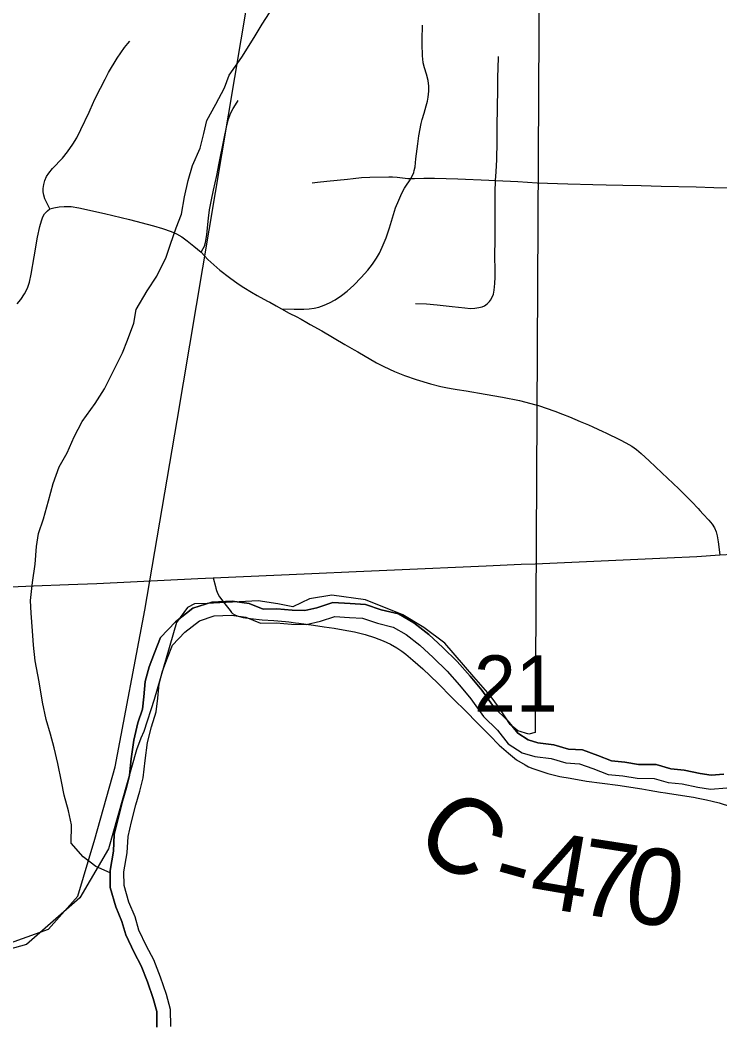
# Model space of a CAD drawing. Extents: x 0 to 191, y 0 to 55.
# Drawn here: x 143.5787 to 143.8392, y 23.9869 to 24.3604 of the extents above; entities that cross this region are included whole.
import ezdxf

# ---------------------------------------------------------------- set-up
doc = ezdxf.new("R2010")
doc.units = 0
for name, color, linetype in [('GM_X_City_Street', 7, 'Continuous'), ('GM_X_Corporation', 7, 'Continuous'), ('GM_X_County_Road', 7, 'Continuous'), ('GM_X_County_Road_Text', 7, 'Continuous'), ('GM_X_Major_River', 7, 'Continuous'), ('GM_X_Minor_River', 7, 'Continuous'), ('GM_X_Rail_Line', 7, 'Continuous'), ('GM_X_Section_Text', 7, 'Continuous'), ('GM_X_State_Route', 7, 'Continuous'), ('GM_X_Township_Road', 7, 'Continuous')]:
    doc.layers.add(name, color=color, linetype=linetype)

msp = doc.modelspace()

# ---------------------------------------------------------------- linework, layer by layer
at = {"layer": 'GM_X_City_Street'}
for points in [[(143.72412, 24.30142), (143.72486, 24.3027), (143.72525, 24.30362), (143.72539, 24.30431), (143.72567, 24.30567), (143.72603, 24.30874), (143.72668, 24.31426), (143.72711, 24.31732), (143.72792, 24.32189), (143.7283, 24.32339), (143.72903, 24.32575), (143.72981, 24.32842), (143.73027, 24.33022), (143.73059, 24.33173), (143.73085, 24.33388), (143.73085, 24.33573), (143.73055, 24.33787), (143.72996, 24.34028), (143.72923, 24.34265), (143.72874, 24.34444), (143.72852, 24.34597), (143.72843, 24.34689), (143.7284, 24.34812), (143.72831, 24.3506), (143.72835, 24.35495), (143.7284, 24.35646), (143.72847, 24.35731), (143.72845, 24.35801), (143.72847, 24.35853)], [(143.58969, 24.29003), (143.58838, 24.2928), (143.58793, 24.29375), (143.58747, 24.29516), (143.58728, 24.29639), (143.58726, 24.29763), (143.58747, 24.29917), (143.58789, 24.30066), (143.58854, 24.30208), (143.58938, 24.30338), (143.59077, 24.30505), (143.59439, 24.30892), (143.59636, 24.31133), (143.59831, 24.31414), (143.59974, 24.31654), (143.60131, 24.31959), (143.60435, 24.32607), (143.60472, 24.32692), (143.6056, 24.3289), (143.60651, 24.33088), (143.60855, 24.33507), (143.61028, 24.33836), (143.61163, 24.34081), (143.61483, 24.34623), (143.61756, 24.35011), (143.61882, 24.35163), (143.61952, 24.35252)], [(143.7515, 24.25398), (143.75259, 24.25473), (143.75345, 24.25559), (143.75381, 24.25608), (143.75441, 24.25713), (143.75485, 24.25827), (143.75516, 24.25976), (143.75535, 24.26224), (143.75545, 24.26464), (143.75549, 24.26632), (143.75549, 24.26738), (143.75548, 24.2682), (143.7554, 24.27149), (143.75542, 24.27487), (143.75545, 24.2764), (143.75549, 24.27824), (143.75551, 24.28099), (143.75556, 24.28407), (143.75553, 24.28686), (143.75554, 24.29736), (143.7556, 24.29952), (143.75566, 24.30064), (143.75583, 24.30384), (143.75611, 24.30848), (143.75625, 24.31498), (143.75628, 24.31839), (143.75631, 24.31962), (143.7564, 24.32892), (143.75645, 24.33356), (143.75655, 24.33851), (143.75664, 24.34314), (143.75671, 24.34592), (143.75673, 24.34684)], [(143.64604, 24.2739), (143.64679, 24.27525), (143.64725, 24.27621), (143.6477, 24.27752), (143.64793, 24.27894), (143.64813, 24.28047), (143.64876, 24.28665), (143.64919, 24.28973), (143.64987, 24.2934), (143.65067, 24.29704), (143.65186, 24.30251), (143.65279, 24.30708), (143.65459, 24.31624), (143.65549, 24.3205), (143.65627, 24.3235), (143.65699, 24.32555), (143.65797, 24.3275), (143.65945, 24.32987), (143.65981, 24.33037)], [(143.6874, 24.29981), (143.68938, 24.30007), (143.69288, 24.30039), (143.70051, 24.30112), (143.70267, 24.30136), (143.70576, 24.30171), (143.70886, 24.3019), (143.71594, 24.30206), (143.71728, 24.302), (143.71901, 24.30183), (143.72107, 24.30161), (143.72302, 24.30144), (143.72412, 24.30142), (143.72547, 24.30139), (143.7289, 24.30149), (143.73293, 24.30152), (143.74163, 24.30121), (143.75312, 24.30075), (143.75566, 24.30064), (143.76399, 24.30027), (143.77111, 24.29978)], [(143.67597, 24.25283), (143.68065, 24.25275), (143.68434, 24.2527), (143.68625, 24.25281), (143.68814, 24.25309), (143.68984, 24.25351), (143.69188, 24.25422), (143.69384, 24.25508), (143.69598, 24.25624), (143.69825, 24.25776), (143.70039, 24.25946), (143.70288, 24.26171), (143.70567, 24.26454), (143.70811, 24.26728), (143.7098, 24.26944), (143.71137, 24.27172), (143.71244, 24.27359), (143.7135, 24.27581), (143.71488, 24.27925), (143.71617, 24.28305), (143.71844, 24.29045), (143.71962, 24.29331), (143.72073, 24.29586), (143.72181, 24.29773), (143.72251, 24.29888), (143.72357, 24.30055), (143.72412, 24.30142)], [(143.57755, 24.25475), (143.57892, 24.25637), (143.58028, 24.25837), (143.58137, 24.26052), (143.58213, 24.26281), (143.58281, 24.26579), (143.58393, 24.27216), (143.58515, 24.27949), (143.586, 24.28346), (143.58657, 24.28558), (143.58713, 24.28707), (143.58779, 24.28821), (143.58833, 24.28888), (143.58889, 24.28938), (143.58969, 24.29003), (143.59121, 24.29051), (143.59316, 24.29086), (143.59508, 24.29095), (143.59768, 24.29089), (143.60055, 24.29048), (143.61003, 24.2884), (143.61935, 24.28607), (143.62838, 24.2838), (143.63167, 24.28281), (143.63491, 24.28164), (143.63692, 24.28074), (143.63884, 24.27966), (143.6409, 24.2782), (143.64332, 24.27621), (143.64604, 24.2739), (143.64859, 24.27122), (143.65303, 24.26726), (143.65659, 24.26448), (143.65988, 24.26219), (143.66193, 24.26081), (143.66481, 24.25903), (143.66697, 24.25782), (143.67075, 24.25574), (143.67157, 24.25531), (143.67397, 24.25393), (143.67597, 24.25283), (143.67881, 24.25125), (143.67962, 24.25082), (143.68091, 24.25018), (143.68141, 24.24994), (143.68323, 24.24895), (143.68536, 24.24777), (143.68669, 24.24702), (143.69099, 24.2446), (143.69955, 24.23958), (143.70306, 24.23757), (143.70441, 24.23681), (143.71137, 24.23277), (143.7141, 24.23134), (143.71803, 24.22955), (143.72175, 24.22804), (143.72612, 24.22651), (143.73145, 24.22491), (143.73532, 24.2239), (143.73772, 24.22337), (143.73985, 24.22304), (143.74137, 24.22278), (143.74474, 24.22228), (143.75177, 24.22111), (143.7582, 24.21999), (143.76461, 24.21872), (143.7707, 24.2171)], [(143.72587, 24.25485), (143.72991, 24.25465), (143.73395, 24.25427), (143.73954, 24.2537), (143.74419, 24.25317), (143.74636, 24.25302), (143.74792, 24.25306), (143.74946, 24.25329), (143.75065, 24.25364), (143.7515, 24.25398)]]:
    msp.add_lwpolyline(points, dxfattribs=at)
at = {"layer": 'GM_X_Corporation'}
msp.add_lwpolyline([(143.77183, 24.38038), (143.77042, 24.09506), (143.76806, 24.09441), (143.76389, 24.09572), (143.76105, 24.09798), (143.75706, 24.10404), (143.75364, 24.10877), (143.74756, 24.11577), (143.73674, 24.12826), (143.72897, 24.13411), (143.72119, 24.13883), (143.70718, 24.14447), (143.69469, 24.14613), (143.68637, 24.14477), (143.68013, 24.1419), (143.67464, 24.14302), (143.66727, 24.14413), (143.64825, 24.1431), (143.64362, 24.1429), (143.64098, 24.14156), (143.63683, 24.13604), (143.63309, 24.12274), (143.6286, 24.10735), (143.62467, 24.09538), (143.62357, 24.09294), (143.62204, 24.08862), (143.61152, 24.05171), (143.60095, 24.03342), (143.58108, 24.01605), (143.49103, 23.99117)], dxfattribs=at)
at = {"layer": 'GM_X_County_Road'}
for points in [[(143.65059, 24.15265), (143.65134, 24.14945), (143.65149, 24.14883), (143.65178, 24.1479), (143.65229, 24.14672), (143.65294, 24.14562), (143.6549, 24.14302)], [(143.6549, 24.14302), (143.65682, 24.14044), (143.6574, 24.13974), (143.65778, 24.13941), (143.65862, 24.13889), (143.65982, 24.13841), (143.66167, 24.13791), (143.66445, 24.13745), (143.66882, 24.13702), (143.67317, 24.13672), (143.67748, 24.13638), (143.67872, 24.13627), (143.68117, 24.13592), (143.68239, 24.13573), (143.68791, 24.13496), (143.6919, 24.13442), (143.69558, 24.13392), (143.69893, 24.13333), (143.70317, 24.13249), (143.70706, 24.13153), (143.71059, 24.13043), (143.71376, 24.12922), (143.71655, 24.12796), (143.71893, 24.12663), (143.72082, 24.12539), (143.7223, 24.12421), (143.7248, 24.12201), (143.72859, 24.1187), (143.73413, 24.11336), (143.73953, 24.10796), (143.7451, 24.10252), (143.74835, 24.09911), (143.75335, 24.09404), (143.75696, 24.09029), (143.76041, 24.08731), (143.76348, 24.08488), (143.76662, 24.08299), (143.76791, 24.08231), (143.76953, 24.08164), (143.77507, 24.07978), (143.7776, 24.0791), (143.7796, 24.07867), (143.78345, 24.07802), (143.78947, 24.07693), (143.80116, 24.07543), (143.81006, 24.07401), (143.8128, 24.07354), (143.81705, 24.07286), (143.81887, 24.07255), (143.82038, 24.07231), (143.82934, 24.07091), (143.83113, 24.07058), (143.83413, 24.06997), (143.83624, 24.0695), (143.83893, 24.06879), (143.84307, 24.06751)]]:
    msp.add_lwpolyline(points, dxfattribs=at)
at = {"layer": 'GM_X_Major_River'}
for points in [[(143.62959, 23.98529), (143.62953, 23.9911), (143.62817, 23.99598), (143.62611, 24.00214), (143.62374, 24.00816), (143.62112, 24.01308), (143.61798, 24.01962), (143.61657, 24.02464), (143.61425, 24.03011), (143.6122, 24.03733), (143.61213, 24.04362), (143.61341, 24.05082), (143.61373, 24.05702), (143.61512, 24.06305), (143.61678, 24.06945), (143.61824, 24.07458), (143.6194, 24.0791), (143.62006, 24.08525), (143.62098, 24.09224), (143.62255, 24.09862), (143.62426, 24.10379), (143.62472, 24.10833), (143.62527, 24.11407), (143.62672, 24.11948), (143.62865, 24.12469), (143.63089, 24.13048), (143.63656, 24.13629), (143.64299, 24.14131), (143.65001, 24.14359), (143.65759, 24.1439), (143.66398, 24.14307), (143.66914, 24.141), (143.67423, 24.14107), (143.68, 24.14056), (143.68468, 24.14046), (143.68908, 24.14146), (143.69506, 24.14347), (143.70157, 24.1431), (143.70718, 24.14274), (143.71312, 24.14076), (143.71953, 24.13919), (143.72521, 24.13586), (143.73083, 24.13159), (143.73603, 24.12669), (143.74137, 24.12146), (143.74614, 24.11601), (143.7505, 24.11076), (143.75514, 24.1044), (143.76023, 24.09942), (143.76393, 24.09475), (143.76776, 24.09226), (143.77135, 24.09116), (143.77738, 24.09048), (143.78276, 24.08888), (143.78805, 24.08855), (143.79374, 24.08644), (143.79879, 24.08448), (143.80375, 24.08403), (143.80887, 24.08318), (143.81538, 24.08306), (143.82089, 24.08156), (143.82586, 24.08107), (143.83186, 24.07978), (143.83586, 24.07919), (143.84058, 24.07955)], [(143.84058, 24.07955), (143.83586, 24.07919), (143.83186, 24.07978), (143.82586, 24.08107), (143.82089, 24.08156), (143.81538, 24.08306), (143.80887, 24.08318), (143.80375, 24.08403), (143.79879, 24.08448), (143.79374, 24.08644), (143.78805, 24.08855), (143.78276, 24.08888), (143.77738, 24.09048), (143.77135, 24.09116), (143.76776, 24.09226), (143.76393, 24.09475), (143.76023, 24.09942), (143.75514, 24.1044), (143.7505, 24.11076), (143.74614, 24.11601), (143.74137, 24.12146), (143.73603, 24.12669), (143.73083, 24.13159), (143.72521, 24.13586), (143.71953, 24.13919), (143.71312, 24.14076), (143.70718, 24.14274), (143.70157, 24.1431), (143.69506, 24.14347), (143.68908, 24.14146), (143.68468, 24.14046), (143.68, 24.14056), (143.67423, 24.14107), (143.66914, 24.141), (143.66398, 24.14307), (143.65759, 24.1439), (143.65001, 24.14359), (143.64299, 24.14131), (143.63656, 24.13629), (143.63089, 24.13048), (143.62865, 24.12469), (143.62672, 24.11948), (143.62527, 24.11407), (143.62472, 24.10833), (143.62426, 24.10379), (143.62255, 24.09862), (143.62098, 24.09224), (143.62006, 24.08525), (143.6194, 24.0791), (143.61824, 24.07458), (143.61678, 24.06945), (143.61512, 24.06305), (143.61373, 24.05702), (143.61341, 24.05082), (143.61213, 24.04362), (143.6122, 24.03733), (143.61425, 24.03011), (143.61657, 24.02464), (143.61798, 24.01962), (143.62112, 24.01308), (143.62374, 24.00816), (143.62611, 24.00214), (143.62817, 23.99598), (143.62953, 23.9911), (143.62959, 23.98529)], [(143.63477, 23.98557), (143.63471, 23.99183), (143.63313, 23.9975), (143.63098, 24.00392), (143.62846, 24.01034), (143.62575, 24.01542), (143.62285, 24.02145), (143.62148, 24.02637), (143.61915, 24.03184), (143.61738, 24.03807), (143.61732, 24.04319), (143.61857, 24.05023), (143.61889, 24.0563), (143.62015, 24.06181), (143.62179, 24.06809), (143.62325, 24.07323), (143.62452, 24.07818), (143.62521, 24.08463), (143.62608, 24.09128), (143.62753, 24.09718), (143.62937, 24.1027), (143.62988, 24.10783), (143.63039, 24.11314), (143.63167, 24.1179), (143.6335, 24.12285), (143.63534, 24.12762), (143.64002, 24.13242), (143.64546, 24.13666), (143.65093, 24.13843), (143.65736, 24.1387), (143.66266, 24.13801), (143.66817, 24.1358), (143.67404, 24.13587), (143.67972, 24.13538), (143.6852, 24.13525), (143.69049, 24.13646), (143.69577, 24.13823), (143.70126, 24.13792), (143.70618, 24.1376), (143.71168, 24.13577), (143.71756, 24.13433), (143.72232, 24.13154), (143.72747, 24.12762), (143.73244, 24.12295), (143.7376, 24.11789), (143.74219, 24.11264), (143.74641, 24.10757), (143.75121, 24.10099), (143.75637, 24.09594), (143.7604, 24.09087), (143.76554, 24.08752), (143.77028, 24.08606), (143.77635, 24.08537), (143.78185, 24.08374), (143.78696, 24.08342), (143.7919, 24.08159), (143.7976, 24.07938), (143.80309, 24.07888), (143.80839, 24.078), (143.81464, 24.07789), (143.81995, 24.07644), (143.82506, 24.07593), (143.83094, 24.07468), (143.83568, 24.07398), (143.84173, 24.07443)]]:
    msp.add_lwpolyline(points, dxfattribs=at)
at = {"layer": 'GM_X_Minor_River'}
msp.add_lwpolyline([(143.61214, 24.04275), (143.6069, 24.04515), (143.60213, 24.04869), (143.59773, 24.05376), (143.59785, 24.06059), (143.59665, 24.06588), (143.59508, 24.07174), (143.59408, 24.07685), (143.59268, 24.08347), (143.5913, 24.08933), (143.58992, 24.09444), (143.58835, 24.09991), (143.58695, 24.10635), (143.58574, 24.11392), (143.58433, 24.12167), (143.5837, 24.12755), (143.58327, 24.13285), (143.58282, 24.13948), (143.58258, 24.14422), (143.58327, 24.15087), (143.58433, 24.15771), (143.58482, 24.16435), (143.58553, 24.1691), (143.58736, 24.17462), (143.58918, 24.18128), (143.59101, 24.18776), (143.59321, 24.19404), (143.59618, 24.1992), (143.59877, 24.20511), (143.60173, 24.21084), (143.60658, 24.21753), (143.61012, 24.22308), (143.61271, 24.22823), (143.61678, 24.23644), (143.61862, 24.2412), (143.62102, 24.24749), (143.62191, 24.25262), (143.626, 24.2595), (143.62953, 24.26504), (143.63305, 24.2721), (143.6347, 24.27687), (143.63672, 24.28296), (143.63874, 24.28811), (143.63981, 24.29457), (143.64126, 24.30065), (143.6429, 24.30617), (143.64567, 24.31266), (143.64712, 24.31817), (143.64821, 24.32293), (143.65155, 24.32904), (143.6547, 24.33515), (143.65654, 24.33991), (143.6612, 24.34661), (143.66585, 24.35387), (143.66882, 24.35884), (143.67292, 24.36515)], dxfattribs=at)
at = {"layer": 'GM_X_Rail_Line'}
msp.add_lwpolyline([(143.27549, 23.89454), (143.36161, 23.93384), (143.46302, 23.97989), (143.50458, 23.99653), (143.54559, 24.00874), (143.57163, 24.0154), (143.58928, 24.02181), (143.60021, 24.03414), (143.60654, 24.05535), (143.614, 24.08224), (143.62508, 24.14058), (143.63707, 24.21122), (143.68239, 24.48087), (143.72503, 24.72385)], dxfattribs=at)
at = {"layer": 'GM_X_State_Route'}
for points in [[(143.77043, 24.15788), (143.79774, 24.15909), (143.81948, 24.16006), (143.83064, 24.16063), (143.83909, 24.16122), (143.84399, 24.16146), (143.84644, 24.16167), (143.84798, 24.16174), (143.84982, 24.16193), (143.85167, 24.16191), (143.85412, 24.16228), (143.85752, 24.16254), (143.85906, 24.16266), (143.86153, 24.16292), (143.864, 24.16311), (143.86771, 24.16347), (143.8714, 24.1639), (143.87294, 24.16402), (143.87507, 24.16434), (143.87723, 24.16454), (143.87968, 24.1649), (143.88183, 24.16512), (143.88457, 24.1656), (143.88676, 24.16591)], [(143.50951, 24.1464), (143.51643, 24.14671), (143.52635, 24.14719), (143.53242, 24.14742), (143.5366, 24.14757), (143.55333, 24.14828), (143.56635, 24.14896), (143.57503, 24.14931), (143.58371, 24.14963), (143.59673, 24.15016), (143.60728, 24.15055), (143.64481, 24.1524), (143.65059, 24.15265), (143.68731, 24.15421), (143.70375, 24.15503), (143.71802, 24.15565), (143.75214, 24.15712), (143.76517, 24.1577), (143.77043, 24.15788)]]:
    msp.add_lwpolyline(points, dxfattribs=at)
at = {"layer": 'GM_X_Township_Road'}
for points in [[(143.77111, 24.29978), (143.7826, 24.29936), (143.79192, 24.29912), (143.79688, 24.29901), (143.80309, 24.29889), (143.8099, 24.29873), (143.81734, 24.29858), (143.83037, 24.29824), (143.83689, 24.29806), (143.84279, 24.29793)], [(143.7707, 24.2171), (143.77158, 24.21686), (143.77769, 24.21466), (143.78056, 24.21366), (143.78312, 24.21264), (143.78709, 24.21093), (143.79022, 24.20959), (143.79191, 24.20885), (143.79557, 24.20713), (143.79669, 24.2066), (143.80201, 24.20406), (143.80421, 24.2029), (143.80637, 24.20164), (143.80812, 24.20044), (143.8098, 24.19895), (143.81282, 24.19626), (143.81758, 24.19179), (143.82383, 24.18575), (143.82869, 24.18092), (143.83108, 24.17846), (143.8317, 24.17777), (143.83297, 24.17641), (143.8351, 24.17412), (143.83628, 24.17263), (143.83714, 24.17129), (143.83776, 24.16979), (143.8382, 24.16824), (143.83858, 24.16606), (143.83909, 24.16122)]]:
    msp.add_lwpolyline(points, dxfattribs=at)

# ---------------------------------------------------------------- texts
at = {"layer": 'GM_X_County_Road_Text'}
for s, rotation, p in [('C', 323.2222, (143.72415, 24.05371)), ('4', 350.2727, (143.76741, 24.03087)), ('7', 351.1822, (143.78515, 24.02783)), ('0', 351.1759, (143.80244, 24.02515)), ('-', 344.3715, (143.75306, 24.03471))]:
    msp.add_text(s, height=0.02841, rotation=rotation, dxfattribs=at).set_placement(p)
at = {"layer": 'GM_X_Section_Text'}
msp.add_text('21', height=0.020928, rotation=0, dxfattribs=at).set_placement((143.74762, 24.10284))

doc.saveas('drawing.dxf')
